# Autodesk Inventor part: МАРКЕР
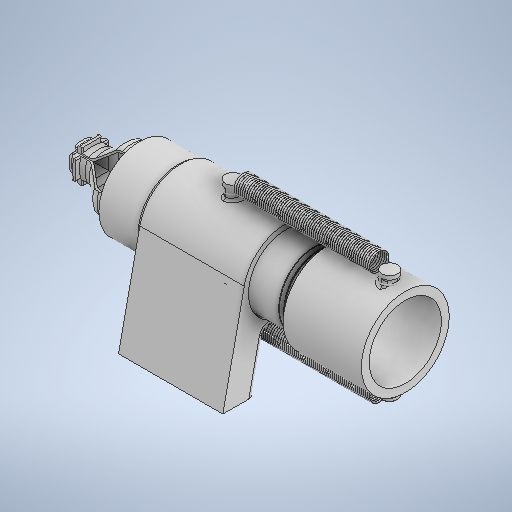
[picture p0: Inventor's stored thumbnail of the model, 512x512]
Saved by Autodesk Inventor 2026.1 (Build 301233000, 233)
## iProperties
Created: 2025-12
Part Number: МАРКЕР
Material: Типовые
Document SubType Name: Modeling
Designer: Yury Melnikov
Density: 1 g/cm^3
Appearance: По умолчанию
Author: Yury Melnikov
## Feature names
1. Вращение1 [Revolution]
2. Вращение2 [Revolution]
3. Пружина2
4. Выдавливание1 [Extrusion]
5. Выдавливание2 [Extrusion]
6. Сдвиг1
7. Сопряжение1 [Fillet]
8. Сопряжение2 [Fillet]
9. Выдавливание3 [Extrusion]
10. Сопряжение3 [Fillet]
11. Сопряжение4 [Fillet]
12. Выдавливание4 [Extrusion]
13. Фаска1 [Chamfer]
14. Зеркальное отражение1 [Mirror]
15. Выдавливание6 [Extrusion]
16. Фаска2 [Chamfer]
17. Фаска3 [Chamfer]
18. Выдавливание7 [Extrusion]
19. Фаска4 [Chamfer]
20. Круговой массив1 [Circular Pattern]
21. Фаска5 [Chamfer]
22. Вращение3 [Revolution]
23. Сопряжение6 [Fillet]
24. Круговой массив6 [Circular Pattern]
25. Выдавливание11 [Extrusion]
26. Выдавливание12 [Extrusion]
27. Выдавливание13 [Extrusion]
28. Выдавливание14 [Extrusion]
29. Выдавливание15 [Extrusion]
30. Выдавливание16 [Extrusion]
31. Выдавливание17 [Extrusion]
32. Сопряжение8 [Fillet]
33. Выдавливание18 [Extrusion]
34. Сопряжение9 [Fillet]
35. Сопряжение10 [Fillet]
36. Зеркальное отражение2 [Mirror]
37. Сопряжение13 [Fillet]
38. Выдавливание22 [Extrusion]
39. Выдавливание23 [Extrusion]
40. Сопряжение14 [Fillet]
41. Выдавливание24 [Extrusion]
42. Фаска7 [Chamfer]
43. Сопряжение15 [Fillet]
44. Сопряжение16 [Fillet]
45. Выдавливание25 [Extrusion]
46. Сопряжение17 [Fillet]
47. Вращение4 [Revolution]
48. Вращение5 [Revolution]
49. Пружина3
50. Выдавливание26 [Extrusion]
51. Выдавливание27 [Extrusion]
52. Выдавливание28 [Extrusion]
53. Фаска8 [Chamfer]
54. Сопряжение18 [Fillet]
55. Фаска9 [Chamfer]
56. Сопряжение19 [Fillet]
57. Вращение6 [Revolution]
58. Пружина4
59. Круговой массив8 [Circular Pattern]
60. Пружина5
61. Пружина6
62. Вращение7 [Revolution]
63. Вращение8 [Revolution]
64. Зеркальное отражение3 [Mirror]
## Parameters: d0 = 19 mm, d1 = 2 mm, d2 = 2 mm, d3 = 1 mm, d7 = 90 deg, d8 = 0.3 mm, d10 = 360 deg, d23 = 1.8 mm, d24 = 0.6 mm, d25 = 2.5 mm, d28 = 0, d29 = 90 deg, d30 = 90 deg, d31 = 0, d32 = 0, d33 = 8 mm, d36 = 360 deg, d39 = 0, d42 = 360 deg, d45 = 0, d46 = 0.2 mm, d47 = 14 mm, d48 = 8 mm, d49 = 40 deg, d50 = 8 mm, d51 = 0, d52 = 0, d53 = 4 mm, d54 = 2 mm, d55 = 2 mm, d56 = 2 mm, d58 = 0, d59 = 1 mm, d60 = 0.5 mm, d61 = 25 mm, d62 = 60 deg, d63 = 15 mm, d64 = -15 mm, d65 = 8 mm, d66 = 0, d72 = 1 mm, d73 = 2 mm, d74 = 45 deg, d75 = 0.15 mm, d76 = 1.8 mm, d77 = 15 mm, d78 = 0, d79 = 1 mm, d80 = 2 mm, d81 = 45 deg, d82 = 1 mm, d83 = 2 mm, d84 = 45 deg, d85 = 3.3 mm, d87 = 0, d88 = 0.5 mm, d89 = 2 mm, d90 = 45 deg, d92 = 360 deg, d94 = 1 mm, d101 = 2 mm, d102 = 2 mm, d103 = 45 deg, d107 = 1.2 mm, d108 = 9 mm, d109 = 25 mm, d110 = 60 deg, d113 = 0.6 mm, d124 = 360 deg, d129 = 1 mm, d130 = 0.6 mm, d131 = 2 mm, d133 = 0, d134 = 3 mm, d135 = 5 mm, d137 = 0, d138 = 2 mm, d140 = 0, d141 = 0.3 mm, d142 = 3 mm, d143 = 22 mm, d144 = 0, d145 = 8 mm, d146 = 0, d147 = 22 mm, d148 = 0, d149 = 6 mm, d151 = 5 mm, d152 = 1 mm, d153 = 0, d154 = 0, d155 = -2.5 mm, d156 = 2 mm, d157 = 5 mm, d158 = 0, d161 = 0, d162 = 1 mm, d163 = 1 mm, d164 = 0, d165 = 1 mm, d166 = 0.5 mm, d184 = 3 mm, d185 = 1 mm, d186 = 35 mm, d188 = 12 mm, d189 = 52.25 mm, d190 = 0, d192 = 0, d193 = 5 mm, d194 = 4 mm, d195 = 28 mm, d198 = 33.85521 mm, d201 = 28 mm, d205 = 0, d206 = 0.5 mm, d207 = 2 mm, d208 = 45 deg, d209 = 2 mm, d210 = 0.7 mm, d211 = 0.8 mm, d213 = 0, d214 = 2 mm, d216 = 0, d217 = 55 deg, d218 = 0.32017 mm, d219 = 0.32017 mm, Эскиз38_ThreadOffset = 0, Эскиз38_MajorRadius = 13.5 mm, d222 = 2 mm, Эскиз38_MinorRadius = 12.01708 mm, d224 = 55 deg, Эскиз38_Pitch = 2 mm, d226 = 0, d227 = 360 deg, d228 = 2.002 mm, d229 = 14 mm, d231 = 0, d232 = 0, d233 = 0, d234 = 0, d235 = 0, d236 = 47.85521 mm, d237 = 3 mm, d238 = 50.75 mm, d239 = 0, d240 = 2 mm, d241 = -21.25 mm, d242 = 23.5 mm, d243 = 12 mm, d244 = 7.5 mm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
